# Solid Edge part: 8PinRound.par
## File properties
Author: conerly
Template: ansi part.par
Last saved by: jccrumbl
Revision: 26
Application: Solid Edge
Density: 0.03699434701 lbm/in^3
Accuracy: 0.990
Material: ABS Plastic, high impact
Face Style: Red
Fill Style: ANSI34(Plastic)
Virtual Style: Red (Shiny)
Coef. of Thermal Exp: 9e-05
Thermal Conductivity: 0.2
Specific Heat: 0.0
Modulus of Elasticity: 1378951400.0
Poisson's Ratio: 0.4
Yield Stress: 31026406.5
Ultimate Stress: 0.0
Elongation: 0.0
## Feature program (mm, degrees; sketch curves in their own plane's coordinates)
sketch for "unnamed Protrusion 1" plane through (0, 0, 0) normal (0, -1, 0) x-axis (1, 0, 0)
  circle centre (0, 0) radius 12.7
extrude "unnamed Protrusion 1" add finite 25.4 along -normal
sketch for "ExtrudedCutout_1" #1 plane through (0, 0, 0) normal (0, -1, 0) x-axis (1, 0, 0)
  circle centre (0, 10.0399) radius 1.27
sketch for "ExtrudedCutout_1" #2 plane through (0, 0, 0) normal (0, -1, 0) x-axis (1, 0, 0)
  circle centre (0, 4.9599) radius 1.27
extrude "ExtrudedCutout_1" cut finite 3.175 along -normal
pattern "unnamed Pattern 1" of "ExtrudedCutout_1"
extrude "unnamed Cutout 1" cut finite 3.175
extrude "unnamed Cutout 2" cut finite 3.175
extrude "unnamed Cutout 3" cut finite 3.175
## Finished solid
Body 1: solid body, 19 faces, 18 edges, 0 vertices.
  Faces by surface: plane 10, cylinder 9
  Edges by curve: circle 18
Bounding box of the edges (mm): 25.400 x 25.400 x 25.400, from (-12.7, 0, -12.7) to (12.7, 25.4, 12.7).
Cylindrical faces by radius (mm): R1.27 x8, R12.7 x1
Planar faces by outward normal: +y 1, -y 9
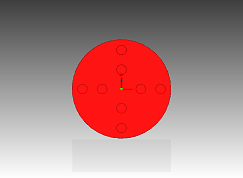
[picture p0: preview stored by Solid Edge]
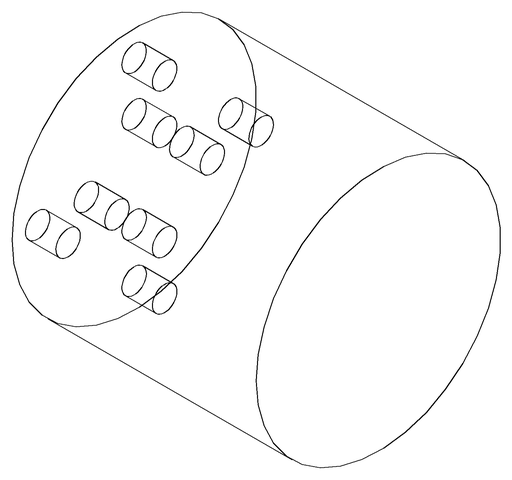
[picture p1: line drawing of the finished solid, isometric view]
